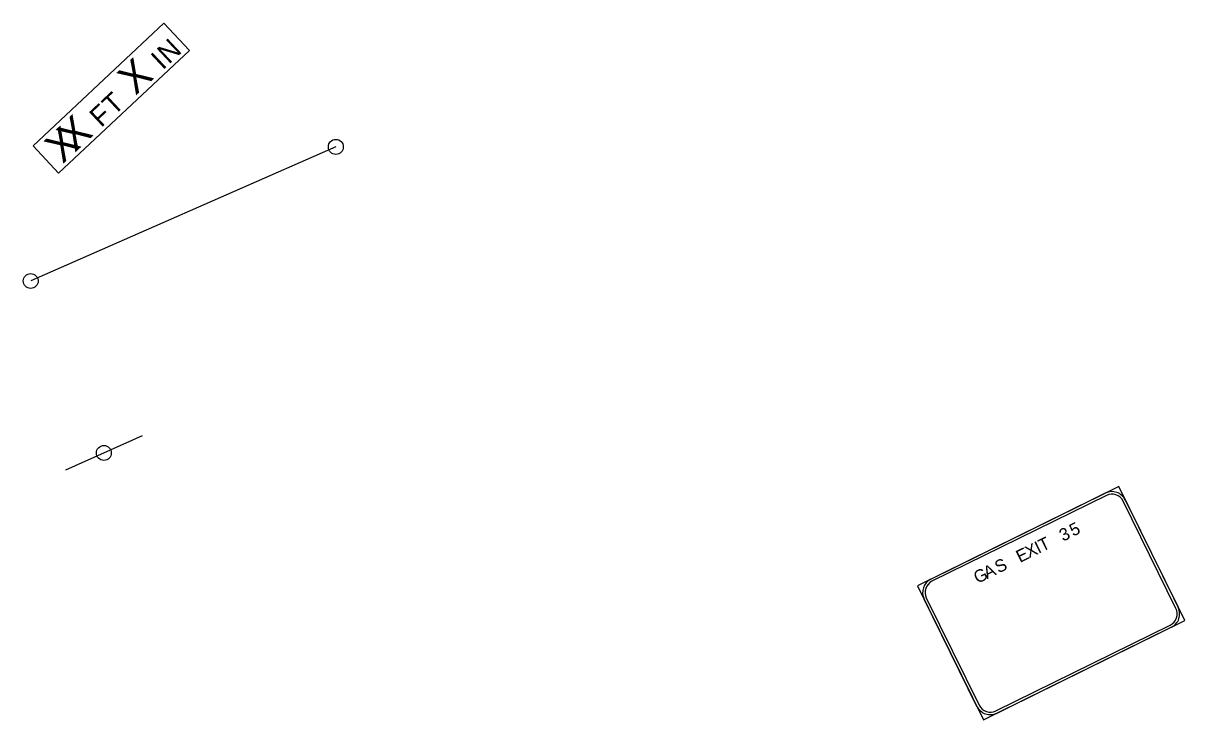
# Model space of a CAD drawing. Extents: x 1581789 to 1622364, y 1043167 to 1103486.
# Drawn here: x 1612958.3 to 1613269, y 1087112.1 to 1087298.5 of the extents above; entities that cross this region are included whole.
import ezdxf

# ---------------------------------------------------------------- set-up
doc = ezdxf.new("R2010")
doc.units = 0
for name, color, linetype in [('Level 15', 7, 'Continuous'), ('RD_PD_ALT1_TX', 7, 'Continuous'), ('RD_PD_PaveDit', 7, 'Continuous')]:
    doc.layers.add(name, color=color, linetype=linetype)

msp = doc.modelspace()

# ---------------------------------------------------------------- linework, layer by layer
at = {"layer": 'Level 15'}
for p, q in [((1613041.94, 1087265.41), (1612960.31, 1087229.52)), ((1612990.13, 1087188.12), (1612969.62, 1087178.88))]:
    msp.add_line(p, q, dxfattribs=at)
for centre in [(1613041.94, 1087265.41), (1612960.31, 1087229.52), (1612979.88, 1087183.5)]:
    msp.add_circle(centre, 2, dxfattribs=at)
at = {"layer": 'RD_PD_ALT1_TX'}
msp.add_lwpolyline([(1612967.78, 1087258.38), (1613002.8, 1087291.2), (1612995.96, 1087298.49), (1612960.94, 1087265.67), (1612967.78, 1087258.38), (1612967.78, 1087258.38)], dxfattribs=at)
at = {"layer": 'RD_PD_PaveDit'}
for points in [[(1613215.22, 1087112.11), (1613269.04, 1087138.63), (1613251.36, 1087174.51), (1613197.54, 1087147.99), (1613215.22, 1087112.11), (1613215.22, 1087112.11)], [(1613201.13, 1087149.76), (1613247.77, 1087172.74)], [(1613248.07, 1087172.15), (1613201.42, 1087149.16)], [(1613266.67, 1087141.93), (1613252.53, 1087170.63)], [(1613253.13, 1087170.92), (1613267.27, 1087142.22)], [(1613213.45, 1087115.7), (1613199.31, 1087144.4)], [(1613199.9, 1087144.7), (1613214.05, 1087115.99)], [(1613218.51, 1087114.48), (1613265.16, 1087137.46)], [(1613265.45, 1087136.86), (1613218.81, 1087113.88)]]:
    msp.add_lwpolyline(points, dxfattribs=at)
for centre, radius, start, end in [((1613249.54, 1087169.16), 4, 26.2335, 116.2337), ((1613249.54, 1087169.16), 3.33, 26.2335, 116.2337), ((1613202.89, 1087146.17), 4, 116.2337, 206.2334), ((1613202.89, 1087146.17), 3.33, 116.2337, 206.2334), ((1613263.68, 1087140.45), 3.33, 296.2336, 26.2338), ((1613263.68, 1087140.45), 4, 296.2336, 26.2338), ((1613217.04, 1087117.47), 4, 206.2334, 296.2336), ((1613217.04, 1087117.47), 3.33, 206.2334, 296.2336)]:
    msp.add_arc(centre, radius, start, end, dxfattribs=at)

# ---------------------------------------------------------------- texts
at = {"layer": 'RD_PD_ALT1_TX'}
for s, height, p in [('N', 5.33, (1612997.27, 1087287.38)), ('X', 8, (1612988.33, 1087279.01)), ('I', 5.33, (1612995.6, 1087285.82)), ('T', 5.33, (1612982.55, 1087273.59)), ('F', 5.33, (1612979.16, 1087270.42)), ('X', 8, (1612972.08, 1087263.78)), ('X', 8, (1612968.84, 1087260.74))]:
    msp.add_text(s, height=height, rotation=43.1415, dxfattribs=at).set_placement(p)
at = {"layer": 'RD_PD_PaveDit'}
for s, p in [('3', (1613236.49, 1087159.75)), ('5', (1613239.2, 1087161.09)), ('X', (1613227.34, 1087155.24)), ('I', (1613229.91, 1087156.51)), ('T', (1613230.93, 1087157.02)), ('E', (1613224.95, 1087154.07)), ('A', (1613216.15, 1087149.73)), ('S', (1613219.21, 1087151.24)), ('G', (1613213.58, 1087148.46))]:
    msp.add_text(s, height=3.33, rotation=26.2335, dxfattribs=at).set_placement(p)

doc.saveas('drawing.dxf')
